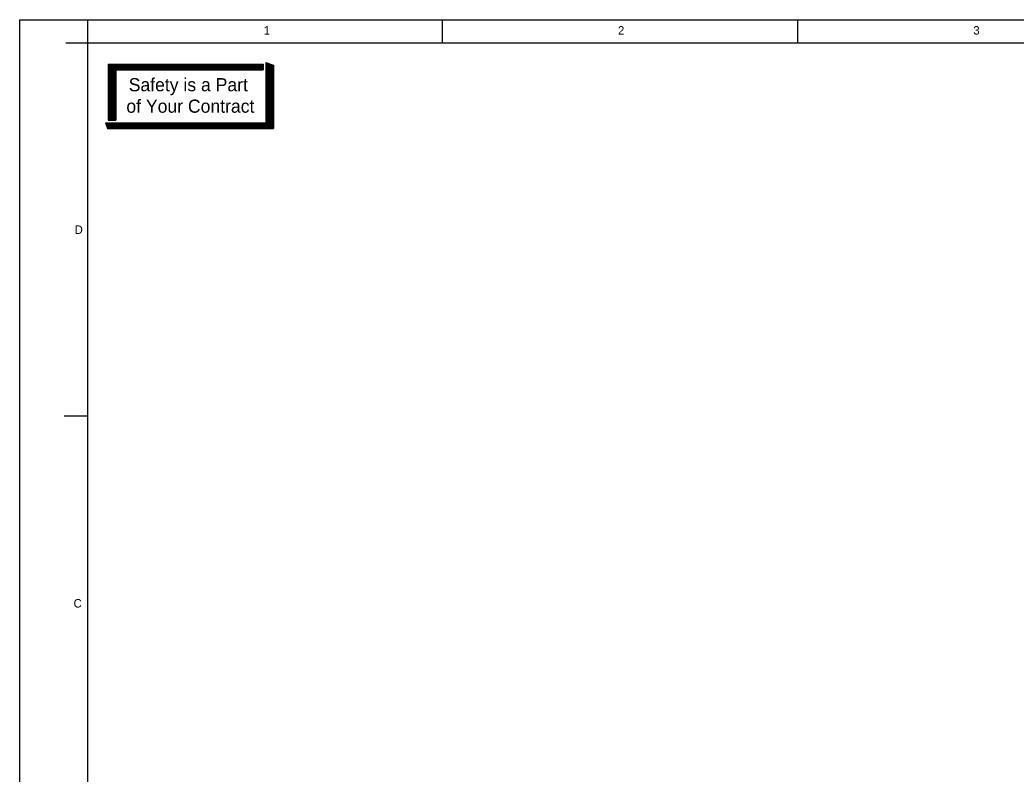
# Model space of a CAD drawing. Extents: x 22369.62 to 22376.4, y 22369.62 to 22372.46.
# Drawn here: x 22369.621 to 22371.455, y 22371.067 to 22372.455 of the extents above; entities that cross this region are included whole.
import ezdxf

# ---------------------------------------------------------------- set-up
doc = ezdxf.new("R2010")
doc.units = 0
for name, color, linetype in [('Level 1', 7, 'Continuous'), ('Level 10', 7, 'Continuous'), ('Level 9', 7, 'Continuous')]:
    doc.layers.add(name, color=color, linetype=linetype)

msp = doc.modelspace()

# ---------------------------------------------------------------- linework, layer by layer
at = {"layer": 'Level 1'}
msp.add_lwpolyline([(22369.6213, 22372.4553), (22373.288, 22372.4553), (22373.288, 22369.6213), (22369.6213, 22369.6213)], close=True, dxfattribs=at)
at = {"layer": 'Level 10'}
for p, q in [((22369.7463, 22372.4133), (22369.7463, 22372.4553)), ((22370.399, 22372.4133), (22370.399, 22372.4553)), ((22371.053, 22372.4133), (22371.053, 22372.4553)), ((22369.7056, 22372.4133), (22369.7459, 22372.4133)), ((22370.074, 22372.377), (22370.074, 22372.2658)), ((22370.074, 22372.377), (22370.0879, 22372.3718)), ((22370.0749, 22372.3767), (22370.0749, 22372.2554)), ((22370.0762, 22372.3762), (22370.0762, 22372.2554)), ((22369.784, 22372.3739), (22370.0687, 22372.3739)), ((22369.784, 22372.3739), (22369.784, 22372.2705)), ((22369.784, 22372.3726), (22370.0687, 22372.3726)), ((22369.784, 22372.3713), (22370.0687, 22372.3713)), ((22369.784, 22372.37), (22370.0687, 22372.37)), ((22369.784, 22372.3687), (22370.0687, 22372.3687)), ((22369.784, 22372.3674), (22370.0687, 22372.3674)), ((22369.784, 22372.3661), (22370.0687, 22372.3661)), ((22369.784, 22372.3648), (22370.0687, 22372.3648)), ((22369.7853, 22372.3739), (22369.7853, 22372.2705)), ((22369.7866, 22372.3739), (22369.7866, 22372.2705)), ((22369.7879, 22372.3739), (22369.7879, 22372.2705)), ((22369.7892, 22372.3739), (22369.7892, 22372.2705)), ((22369.7905, 22372.3739), (22369.7905, 22372.2705)), ((22369.7918, 22372.3739), (22369.7918, 22372.2705)), ((22369.7931, 22372.3739), (22369.7931, 22372.2705)), ((22369.7944, 22372.3739), (22369.7944, 22372.2705)), ((22369.7957, 22372.3739), (22369.7957, 22372.2705)), ((22369.797, 22372.3739), (22369.797, 22372.2705)), ((22369.7979, 22372.3635), (22370.0687, 22372.3635)), ((22369.7979, 22372.3635), (22369.7979, 22372.2705)), ((22370.0687, 22372.3739), (22370.0687, 22372.3635)), ((22370.0775, 22372.3757), (22370.0775, 22372.2554)), ((22370.0788, 22372.3752), (22370.0788, 22372.2554)), ((22370.0801, 22372.3747), (22370.0801, 22372.2554)), ((22370.0814, 22372.3742), (22370.0814, 22372.2554)), ((22370.0827, 22372.3737), (22370.0827, 22372.2554)), ((22370.084, 22372.3732), (22370.084, 22372.2554)), ((22370.0853, 22372.3728), (22370.0853, 22372.2554)), ((22370.0866, 22372.3718), (22370.0866, 22372.2554)), ((22370.0879, 22372.3718), (22370.0879, 22372.2554)), ((22369.7787, 22372.2658), (22370.074, 22372.2658)), ((22369.7787, 22372.2658), (22369.7826, 22372.2554)), ((22369.784, 22372.2705), (22369.7979, 22372.2705)), ((22369.7792, 22372.2645), (22370.0749, 22372.2645)), ((22369.7797, 22372.2632), (22370.0749, 22372.2632)), ((22369.7802, 22372.2619), (22370.0749, 22372.2619)), ((22369.7807, 22372.2606), (22370.0749, 22372.2606)), ((22369.7812, 22372.2593), (22370.0749, 22372.2593)), ((22369.7817, 22372.258), (22370.0749, 22372.258)), ((22369.7821, 22372.2567), (22370.0749, 22372.2567)), ((22369.7826, 22372.2554), (22370.0879, 22372.2554)), ((22369.703, 22371.7263), (22369.745, 22371.7263))]:
    msp.add_line(p, q, dxfattribs=at)
at = {"layer": 'Level 9'}
for p, q in [((22369.7463, 22369.6633), (22369.7463, 22372.4133)), ((22369.7463, 22372.4133), (22373.017, 22372.4133))]:
    msp.add_line(p, q, dxfattribs=at)

# ---------------------------------------------------------------- texts
at = {"layer": 'Level 1'}
for s, p in [('1', (22370.07, 22372.4283)), ('2', (22370.722, 22372.4283)), ('3', (22371.376, 22372.4283)), ('D', (22369.722, 22372.0613)), ('C', (22369.72, 22371.3733))]:
    msp.add_text(s, height=0.0156, dxfattribs=at).set_placement(p)
at = {"layer": 'Level 10'}
for s, p in [('Safety is a Part', (22369.8215, 22372.3239)), ('of Your Contract', (22369.8172, 22372.2844))]:
    msp.add_text(s, height=0.024198, dxfattribs=at).set_placement(p)

doc.saveas('drawing.dxf')
